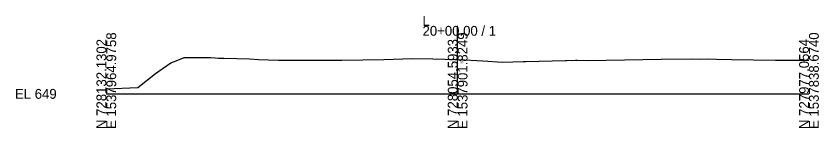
# Model space of a CAD drawing. Extents: x -26 to 1203, y -10 to 9522.
# Drawn here: x 974.3 to 1202.8, y 1490.3 to 1522.1 of the extents above; entities that cross this region are included whole.
import ezdxf

# ---------------------------------------------------------------- set-up
doc = ezdxf.new("R2010")
doc.units = 0
for name, color, linetype in [('Default', 7, 'Continuous'), ('Exist Cross Section Cell', 7, 'Continuous'), ('Exist XS Center Line Elevation Label', 7, 'Continuous'), ('Exist XS Ground Line', 7, 'Continuous')]:
    doc.layers.add(name, color=color, linetype=linetype)

msp = doc.modelspace()

# ---------------------------------------------------------------- linework, layer by layer
at = {"layer": 'Exist Cross Section Cell'}
for p, q in [((1100, 1500), (1100, 1519.33)), ((1000, 1500), (1100, 1500)), ((1100, 1500), (1200, 1500))]:
    msp.add_line(p, q, dxfattribs=at)
at = {"layer": 'Exist XS Ground Line'}
msp.add_lwpolyline([(1000, 1501.44), (1008.96, 1501.84), (1013.99, 1505.81), (1018.37, 1508.82), (1019.9, 1509.35), (1022.14, 1510.31), (1029.72, 1510.3), (1030.95, 1510.25), (1031.97, 1510.15), (1033.49, 1510.16), (1040.76, 1509.93), (1043.32, 1509.74), (1049, 1509.59), (1066.43, 1509.57), (1066.56, 1509.57), (1066.72, 1509.57), (1067.01, 1509.57), (1078.97, 1509.73), (1087.11, 1510.09), (1092.95, 1509.93), (1100, 1509.76), (1100.28, 1509.76), (1107.19, 1509.38), (1112.79, 1509.04), (1118.66, 1509.19), (1119.42, 1509.21), (1130.71, 1509.5), (1131.04, 1509.5), (1133.53, 1509.57), (1134.04, 1509.59), (1137.1, 1509.45), (1157.93, 1509.86), (1166.59, 1509.92), (1168.77, 1509.9), (1171.43, 1509.93), (1173.71, 1509.83), (1177.96, 1509.82), (1190.47, 1509.6), (1193.91, 1509.63), (1199.86, 1509.58), (1200, 1509.58)], dxfattribs=at)

# ---------------------------------------------------------------- texts
at = {"layer": 'Default'}
msp.add_text('-', height=0.0001, dxfattribs=at).set_placement((1000, 1500))
msp.add_text('-', height=0.0001, dxfattribs=at).set_placement((1000, 1500))
msp.add_text('-', height=0.0001, dxfattribs=at).set_placement((1000, 1500))
at = {"layer": 'Exist Cross Section Cell'}
for s, p in [('L', (1090, 1519.33)), ('20+00.00 / 1', (1090, 1516.53)), ('EL 649', (974, 1498.6))]:
    msp.add_text(s, height=2.8, dxfattribs=at).set_placement(p)
for s, p in [('N 728132.1302', (1000, 1490)), ('E 1537964.9758', (1002.8, 1490)), ('N 728054.5933', (1100, 1490)), ('E 1537901.8249', (1102.8, 1490)), ('N 727977.0564', (1200, 1490)), ('E 1537838.6740', (1202.8, 1490))]:
    msp.add_text(s, height=2.8, rotation=90, dxfattribs=at).set_placement(p)
at = {"layer": 'Exist XS Center Line Elevation Label'}
msp.add_text('658.76', height=0.75, dxfattribs=at).set_placement((1098.47, 1508.65))

doc.saveas('drawing.dxf')
